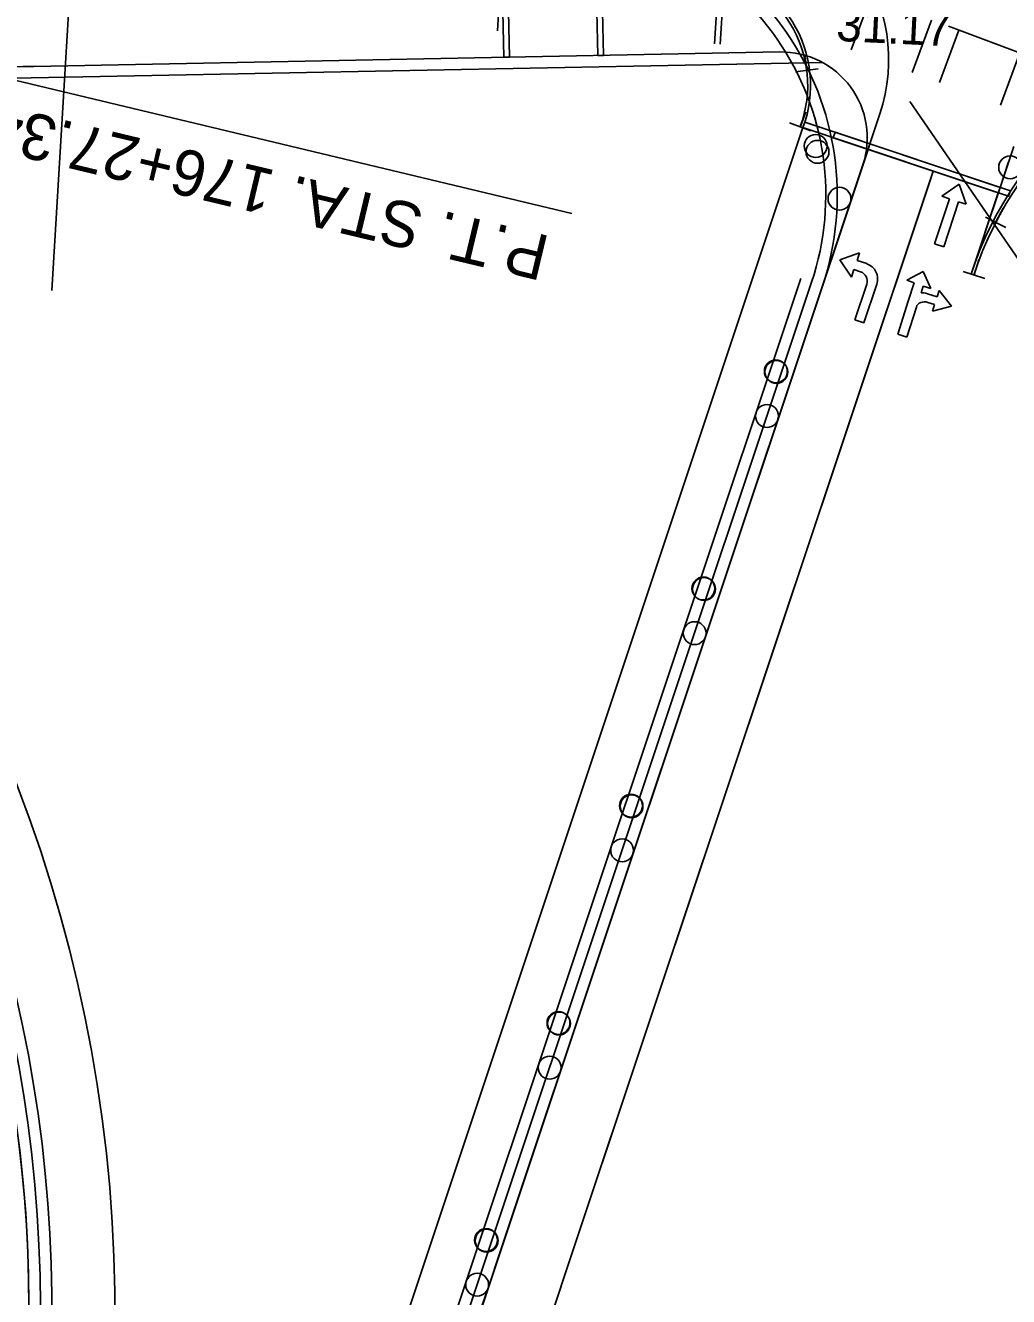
# Model space of a CAD drawing. Extents: x 659657 to 668193, y 633084 to 648639.
# Drawn here: x 662595.7 to 662767.5, y 642149.8 to 642371.9 of the extents above; entities that cross this region are included whole.
import ezdxf

# ---------------------------------------------------------------- set-up
doc = ezdxf.new("R2010")
doc.units = 0
for name, color, linetype in [('R_MOT_Stage 1A_Striping', 7, 'Continuous'), ('R_MOT_Stage 1B_Striping', 7, 'Continuous'), ('R_MOT_Stage 1C', 7, 'Continuous'), ('R_MOT_Stage 1C_Striping', 7, 'Continuous'), ('R_MOT_Stage 1C_Striping_PPM', 7, 'Continuous'), ('R_MOT_Stage 2', 7, 'Continuous'), ('R_MOT_Stage 2_Striping', 7, 'Continuous'), ('R_MOT_Stage 2_Striping_PPM', 7, 'Continuous'), ('R_MOT_Stage 3', 7, 'Continuous'), ('R_MOT_Stage 3_Striping', 7, 'Continuous'), ('R_MOT_Stage 3_Striping_PPM', 7, 'Continuous'), ('R_MOT_Stage 4', 7, 'Continuous'), ('R_MOT_Stage 4_Striping', 7, 'Continuous'), ('R_MOT_Stage 4_Striping_PPM', 7, 'Continuous'), ('R_MOT_Stage 5', 7, 'Continuous'), ('R_MOT_Stage 5_Striping', 7, 'Continuous'), ('R_MOT_Stage 5_Striping_PPM', 7, 'Continuous'), ('T_SIGNAL CONTROL CABINET', 7, 'Continuous'), ('TEMP_SIGNAL_POLES_STAGE 3', 7, 'Continuous'), ('TEXT_TEMP_SIGNAL_POLES_STAGE 2', 7, 'Continuous')]:
    doc.layers.add(name, color=color, linetype=linetype)

msp = doc.modelspace()

# ---------------------------------------------------------------- linework, layer by layer
at = {"layer": 'R_MOT_Stage 1A_Striping'}
msp.add_lwpolyline([(662565.09, 642369.19), (662691.25, 642339)], dxfattribs=at)
at = {"layer": 'R_MOT_Stage 1B_Striping'}
msp.add_lwpolyline([(662565.09, 642369.19), (662691.25, 642339)], dxfattribs=at)
at = {"layer": 'R_MOT_Stage 1C'}
for p, q in [((662731.24, 642327.65), (662661.28, 642118.03)), ((662733.13, 642327.02), (662663.18, 642117.4))]:
    msp.add_line(p, q, dxfattribs=at)
for centre in [(662733.84, 642350.82), (662734.15, 642349.79), (662726.88, 642311.44), (662726.98, 642311.34), (662714.22, 642273.5), (662714.32, 642273.4), (662701.56, 642235.56), (662701.66, 642235.45), (662688.89, 642197.61), (662688.99, 642197.51), (662676.23, 642159.67), (662676.33, 642159.57)]:
    msp.add_circle(centre, 2, dxfattribs=at)
msp.add_arc((662687.6, 642342.21), 48, 341.5452, 87.7297, dxfattribs=at)
at = {"layer": 'R_MOT_Stage 1C_Striping'}
for p, q in [((662768.45, 642350.7), (662761.02, 642328.43)), ((662690.14, 642153.97), (662754, 642345.31)), ((662665.08, 642116.77), (662735.03, 642326.38)), ((662665.08, 642116.77), (662735.03, 642326.38))]:
    msp.add_line(p, q, dxfattribs=at)
msp.add_lwpolyline([(662736.91, 642352.25), (662765.75, 642342.62), (662766.07, 642343.57), (662737.23, 642353.2)], close=True, dxfattribs=at)
msp.add_arc((662687.6, 642342.21), 50, 341.5452, 87.7297, dxfattribs=at)
at = {"layer": 'R_MOT_Stage 1C_Striping_PPM'}
msp.add_line((662676.46, 642112.97), (662690.14, 642153.97), dxfattribs=at)
at = {"layer": 'R_MOT_Stage 2'}
for centre in [(662767.83, 642347.07), (662738, 642341.59), (662725.33, 642303.64), (662712.67, 642265.7), (662700.01, 642227.76), (662687.35, 642189.81), (662674.68, 642151.87)]:
    msp.add_circle(centre, 2, dxfattribs=at)
at = {"layer": 'R_MOT_Stage 2_Striping'}
for p, q in [((662735.03, 642326.38), (662745.05, 642356.41)), ((662766.07, 642343.57), (662767.56, 642348.04)), ((662690.14, 642153.97), (662754, 642345.31)), ((662765.75, 642342.62), (662761.02, 642328.43)), ((662678.76, 642157.77), (662735.03, 642326.38))]:
    msp.add_line(p, q, dxfattribs=at)
msp.add_lwpolyline([(662742.99, 642350.22), (662765.75, 642342.62), (662766.07, 642343.57), (662743.3, 642351.17)], close=True, dxfattribs=at)
for centre, radius, start, end in [((662716.6, 642365.91), 30, 341.5452, 89.9265), ((662207.95, 642311.58), 495.3, 305.927, 341.9079)]:
    msp.add_arc(centre, radius, start, end, dxfattribs=at)
at = {"layer": 'R_MOT_Stage 2_Striping_PPM'}
msp.add_line((662676.46, 642112.97), (662690.14, 642153.97), dxfattribs=at)
at = {"layer": 'R_MOT_Stage 3'}
msp.add_line((662579.5, 642362.38), (662735.08, 642365.38), dxfattribs=at)
for centre in [(662738, 642341.59), (662725.33, 642303.64), (662712.67, 642265.7), (662700.01, 642227.76), (662687.35, 642189.81), (662674.68, 642151.87)]:
    msp.add_circle(centre, 2, dxfattribs=at)
msp.add_arc((662357.6, 642147.63), 240.73, 266.9595, 67.6298, dxfattribs=at)
at = {"layer": 'R_MOT_Stage 3_Striping'}
for p, q in [((662695.17, 642396.61), (662695.74, 642366.62)), ((662696.74, 642366.64), (662696.17, 642396.63)), ((662597.18, 642364.72), (662727.56, 642367.23)), ((662695.74, 642366.62), (662696.74, 642366.64)), ((662735.03, 642326.38), (662742.07, 642347.49)), ((662735.03, 642326.38), (662742.07, 642347.49)), ((662690.14, 642153.97), (662754, 642345.31)), ((662765.75, 642342.62), (662761.02, 642328.43)), ((662678.76, 642157.77), (662735.03, 642326.38))]:
    msp.add_line(p, q, dxfattribs=at)
msp.add_lwpolyline([(662736.91, 642352.25), (662765.75, 642342.62), (662766.07, 642343.57), (662737.23, 642353.2)], close=True, dxfattribs=at)
for centre, radius, start, end in [((662357.6, 642147.63), 238.73, 266.9496, 69.9031), ((662727.85, 642352.23), 15, 341.5452, 91.1014), ((662582.54, 643126.58), 762, 266.54523, 271.10143), ((662207.95, 642311.58), 495.3, 305.927, 341.9079)]:
    msp.add_arc(centre, radius, start, end, dxfattribs=at)
at = {"layer": 'R_MOT_Stage 3_Striping_PPM'}
msp.add_line((662676.46, 642112.97), (662690.14, 642153.97), dxfattribs=at)
at = {"layer": 'R_MOT_Stage 4'}
for centre in [(662738, 642341.59), (662725.33, 642303.64), (662712.67, 642265.7), (662700.01, 642227.76), (662687.35, 642189.81), (662674.68, 642151.87)]:
    msp.add_circle(centre, 2, dxfattribs=at)
at = {"layer": 'R_MOT_Stage 4_Striping'}
for p, q in [((662680.32, 642366.33), (662679.75, 642395.82)), ((662678.75, 642395.8), (662679.32, 642366.3)), ((662597.18, 642364.72), (662727.56, 642367.23)), ((662597.18, 642364.72), (662727.56, 642367.23)), ((662679.32, 642366.3), (662680.32, 642366.33)), ((662735.03, 642326.38), (662742.07, 642347.49)), ((662690.14, 642153.97), (662754, 642345.31)), ((662765.75, 642342.62), (662761.02, 642328.43)), ((662678.76, 642157.77), (662735.03, 642326.38))]:
    msp.add_line(p, q, dxfattribs=at)
msp.add_lwpolyline([(662736.91, 642352.25), (662765.75, 642342.62), (662766.07, 642343.57), (662737.23, 642353.2)], close=True, dxfattribs=at)
for centre, radius, start, end in [((662357.6, 642147.63), 238.73, 266.9496, 69.9031), ((662727.85, 642352.23), 15, 341.5452, 91.1014), ((662582.54, 643126.58), 762, 266.54523, 271.10143), ((662582.54, 643126.58), 762, 266.54523, 271.10143), ((662207.95, 642311.58), 495.3, 305.927, 341.9079)]:
    msp.add_arc(centre, radius, start, end, dxfattribs=at)
at = {"layer": 'R_MOT_Stage 4_Striping_PPM'}
msp.add_line((662676.46, 642112.97), (662690.14, 642153.97), dxfattribs=at)
at = {"layer": 'R_MOT_Stage 5'}
for p, q in [((662732.28, 642364.08), (662731.93, 642366.77)), ((662734.25, 642364.27), (662730.3, 642363.76)), ((662731.16, 642354.23), (662732.12, 642356.77)), ((662732.99, 642353.48), (662729.27, 642354.88)), ((662767.08, 642336.57), (662763.54, 642338.39)), ((662765.34, 642337.53), (662766.59, 642339.94)), ((662761.51, 642328.3), (662762.34, 642330.89)), ((662763.38, 642327.65), (662759.59, 642328.86))]:
    msp.add_line(p, q, dxfattribs=at)
at = {"layer": 'R_MOT_Stage 5_Striping'}
for centre, radius, start, end in [((662711.93, 642361.4), 21.01, 339.4107, 84.4542), ((662818.64, 642309.97), 60.5, 93.3216, 162.2589)]:
    msp.add_arc(centre, radius, start, end, dxfattribs=at)
at = {"layer": 'R_MOT_Stage 5_Striping_PPM'}
for p, q in [((662731.6, 642354.02), (662653.7, 642120.56)), ((662742.99, 642350.22), (662678.76, 642157.77)), ((662754.37, 642346.42), (662690.14, 642153.97)), ((662665.08, 642116.77), (662678.76, 642157.77)), ((662676.46, 642112.97), (662690.14, 642153.97))]:
    msp.add_line(p, q, dxfattribs=at)
msp.add_lwpolyline([(662731.6, 642354.02), (662767.54, 642342.03), (662767.86, 642342.98), (662731.92, 642354.97)], close=True, dxfattribs=at)
for radius, end in [(238.73, 86.5452), (253.73, 62.8692)]:
    msp.add_arc((662357.6, 642147.63), radius, 156.1234, end, dxfattribs=at)
at = {"layer": 'T_SIGNAL CONTROL CABINET'}
for p, q in [((662678.22, 642370.94), (662684.25, 642470.76)), ((662722.18, 642468.47), (662716.16, 642368.65)), ((662717.15, 642368.59), (662723.18, 642468.41)), ((662606.37, 642425.37), (662600.35, 642325.55)), ((662755.87, 642342.03), (662758.91, 642344.11)), ((662758.91, 642344.11), (662760.15, 642340.63)), ((662757.2, 642341.59), (662754.63, 642333.73)), ((662755.87, 642342.03), (662757.2, 642341.59)), ((662758.81, 642341.07), (662756.24, 642333.2)), ((662758.81, 642341.07), (662760.15, 642340.63)), ((662754.63, 642333.73), (662756.24, 642333.2)), ((662741.51, 642332.15), (662738.03, 642330.94)), ((662741.51, 642332.15), (662741.07, 642330.81)), ((662738.03, 642330.94), (662740.09, 642327.88)), ((662740.53, 642329.21), (662740.09, 642327.88)), ((662741.69, 642328.83), (662740.53, 642329.21)), ((662742.76, 642330.25), (662741.07, 642330.81)), ((662752.63, 642328.9), (662749.76, 642327.35)), ((662751.07, 642326.89), (662749.76, 642327.35)), ((662753.95, 642325.89), (662752.63, 642328.9)), ((662742.75, 642326.69), (662740.67, 642320.44)), ((662744.53, 642326.69), (662742.27, 642319.91)), ((662751.07, 642326.89), (662749.99, 642323.71)), ((662752.64, 642326.34), (662752.25, 642325.17)), ((662753.95, 642325.89), (662752.64, 642326.34)), ((662753.35, 642325), (662755.04, 642324.44)), ((662755.39, 642325.56), (662755.04, 642324.44)), ((662755.39, 642325.56), (662757.6, 642322.84)), ((662749.99, 642323.71), (662748.18, 642317.94)), ((662751.43, 642322.66), (662749.78, 642317.4)), ((662753.46, 642323.48), (662754.61, 642323.09)), ((662754.61, 642323.09), (662754.26, 642321.97)), ((662757.6, 642322.84), (662754.26, 642321.97)), ((662740.67, 642320.44), (662742.27, 642319.91)), ((662749.78, 642317.4), (662748.18, 642317.94))]:
    msp.add_line(p, q, dxfattribs=at)
for centre, radius, start, end in [((662711.93, 642361.4), 20.51, 339.4107, 84.4289), ((662357.6, 642147.63), 242.73, 266.9693, 66.2972), ((662818.64, 642309.97), 60, 93.3216, 162.2589), ((662741.86, 642327.58), 2.81, 341.5452, 71.5452), ((662741.15, 642327.23), 1.69, 341.5452, 71.5452)]:
    msp.add_arc(centre, radius, start, end, dxfattribs=at)
for centre, major_axis, end_param in [((662752.64, 642322.76), (-2.63, 1), 5.162885), ((662753.03, 642322.13), (-1.58, 0.6), 6.330459)]:
    msp.add_ellipse(centre, major_axis=major_axis, ratio=0.836684, start_param=4.759662, end_param=end_param, dxfattribs=at)
at = {"layer": 'TEMP_SIGNAL_POLES_STAGE 3'}
msp.add_lwpolyline([(662565.09, 642369.19), (662691.25, 642339)], dxfattribs=at)
at = {"layer": 'TEXT_TEMP_SIGNAL_POLES_STAGE 2'}
for p, q in [((662743.41, 642376.77), (662740.03, 642367.62)), ((662754.1, 642372.81), (662750.71, 642363.66)), ((662757.02, 642371.72), (662771.51, 642366.35)), ((662758.85, 642371.05), (662755.46, 642361.9)), ((662769.54, 642367.08), (662766.15, 642357.94)), ((662750.29, 642358.55), (662887.64, 642158.79))]:
    msp.add_line(p, q, dxfattribs=at)

# ---------------------------------------------------------------- texts
msp.add_text('31.17', height=6, rotation=357.2199).set_placement((662737.34, 642369.18))
at = {"layer": 'R_MOT_Stage 1A_Striping'}
msp.add_text('P.T. STA. 176+27.34', height=8, rotation=166.5452, dxfattribs=at).set_placement((662687.69, 642334.98))
at = {"layer": 'R_MOT_Stage 1B_Striping'}
msp.add_text('P.T. STA. 176+27.34', height=8, rotation=166.5452, dxfattribs=at).set_placement((662687.69, 642334.98))
at = {"layer": 'TEMP_SIGNAL_POLES_STAGE 3'}
msp.add_text('P.T. STA. 176+27.34', height=8, rotation=166.5452, dxfattribs=at).set_placement((662687.69, 642334.98))

doc.saveas('drawing.dxf')
